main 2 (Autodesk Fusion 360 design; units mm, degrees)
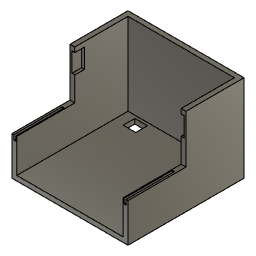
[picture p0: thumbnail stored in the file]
base_feature "基础特征"
sketch "草图" plane through (0, 0, 0) normal (0, 0, -1) x axis (1, 0, 0)
  line L1 (-32, -52) -> (-32, -40)
  line L2 (-45, -52) -> (-32, -52)
  line L3 (-45, -40) -> (-45, -52)
  line L4 (-32, -40) -> (-45, -40)
  line L5 (-60, 60) -> (60, 60)
  line L6 (-60, -60) -> (-60, 60)
  line L7 (60, -60) -> (-60, -60)
  line L8 (60, 60) -> (60, -60)
  line L9 (48, -50) -> (35, -50)
  line L10 (48, -37) -> (48, -50)
  line L11 (35, -37) -> (48, -37)
  line L12 (35, -50) -> (35, -37)
  point P10 (35, -50)
  point P11 (48, -50)
  horizontal L9
  vertical L10
  horizontal L11
  vertical L12
  dimension "d1" distance P10 P11 = 13
  dimension "d2" distance L9 L11 = 13
  dimension "d3" distance L7 L9 = 10
extrude "拉伸" cut sketch "草图" profile of L9 L10 L11 L12 against normal blind 30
